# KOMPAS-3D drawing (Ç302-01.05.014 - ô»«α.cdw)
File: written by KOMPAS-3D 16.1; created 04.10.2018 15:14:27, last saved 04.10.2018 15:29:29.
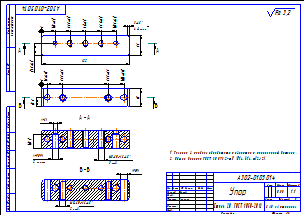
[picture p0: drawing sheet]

Sheet 1: A3, landscape

Title block, sheet 1: name: Упор; designation: А302-01.05.014; material: Сталь 20  ГОСТ 1050-2013; mass: 0,58; scale: 1:1; sheets: 1; organisation: ЗАО «Астерион»; sheet format: A3; stored path: \\192.168.87.28\Konstructor_doc\Мембранные насосы\Мембранный электропривод\А302-00.00.000 - ASTRA-302 (МЭ200)\3Д ПВХ\А302-01.05.014 - Упор.cdw; drawn by: Милов; technical control: Лучихин

Views: Вид 1, Вид:1, Проекционный вид 2, Разрез А-А, Разрез Б-Б
Referenced files in \\192.168.87.28\Konstructor_doc\Мембранные насосы\Мембранный электропривод\А302-00.00.000 - ASTRA-302 (МЭ200)\3Д ПВХ\Отработка\: Упор-1.m3d
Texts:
  Размеры в скобках обработать совместно с сопрягаемой деталью.
  Общие допуски ГОСТ 30893.2-тК (H14, h14,  t2/2).
  Ra 3,2
Dimensions and other numbers on the sheet: 28; 16,5±0,1; 19±0,1; 39,5±0,1; 61±0,1; 82,5±0,1; 103±0,1; 122; 3; 4 фаски; 8±0,2; 29,5±0,2; 92,5±0,2; 114±0,2; 25; 12,5; 19,5; 6; 9; 2 места; -6Н/1,6 45; 3 отв.; 2 отв.; 1:1; 1; 0,58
